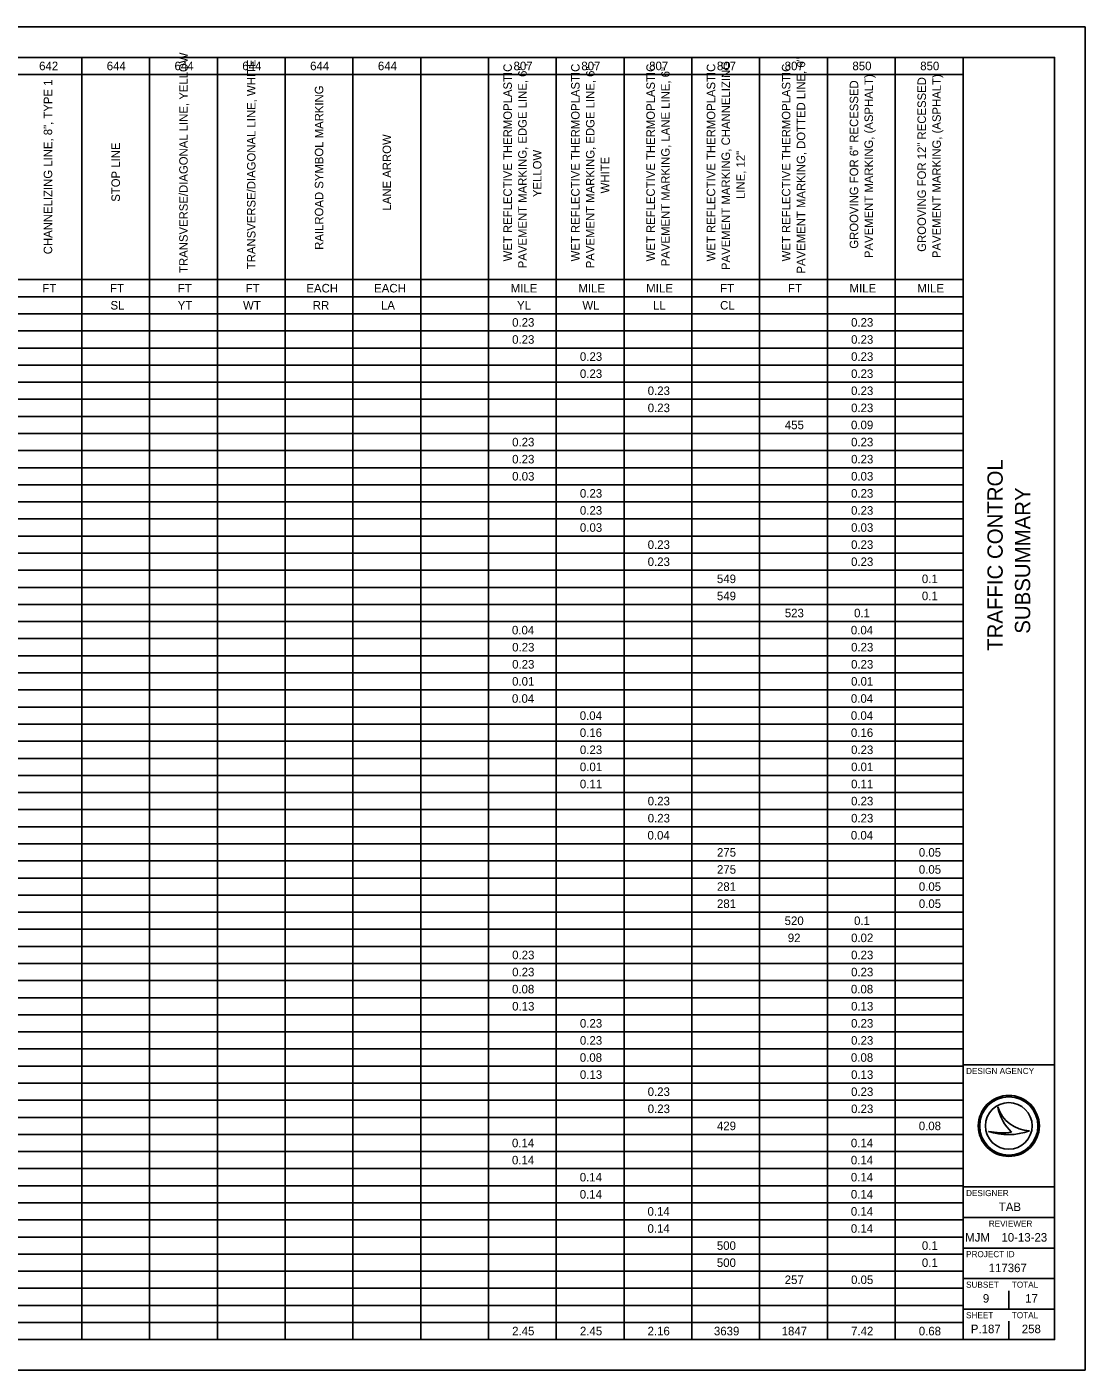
# Model space of a CAD drawing. Extents: x 0 to 34, y 0 to 22.
# Drawn here: x 16.67 to 34, y 0 to 22 of the extents above; entities that cross this region are included whole.
import ezdxf

# ---------------------------------------------------------------- set-up
doc = ezdxf.new("R2010")
doc.units = 0
for name, color, linetype in [('Default', 7, 'Continuous'), ('SH_Border', 7, 'Continuous'), ('SH_Cut_Line', 7, 'Continuous'), ('SH_Data', 7, 'Continuous')]:
    doc.layers.add(name, color=color, linetype=linetype)

msp = doc.modelspace()

# ---------------------------------------------------------------- linework, layer by layer
at = {"layer": 'Default'}
for p, q in [((1.5, 21.5), (32, 21.5)), ((17.566, 21.5), (17.566, 0.5)), ((18.677, 21.5), (18.677, 0.5)), ((19.787, 21.5), (19.787, 0.5)), ((20.897, 21.5), (20.897, 0.5)), ((22.007, 21.5), (22.007, 0.5)), ((23.118, 21.5), (23.118, 0.5)), ((24.228, 21.5), (24.228, 0.5)), ((25.338, 21.5), (25.338, 0.5)), ((26.449, 21.5), (26.449, 0.5)), ((27.559, 21.5), (27.559, 0.5)), ((28.669, 21.5), (28.669, 0.5)), ((29.779, 21.5), (29.779, 0.5)), ((30.89, 21.5), (30.89, 0.5)), ((32, 21.5), (32, 0.5)), ((8.684, 21.22), (32, 21.22)), ((8.684, 17.86), (32, 17.86)), ((1.5, 17.58), (32, 17.58)), ((1.5, 17.3), (32, 17.3)), ((1.5, 17.02), (32, 17.02)), ((1.5, 16.74), (32, 16.74)), ((1.5, 16.46), (32, 16.46)), ((1.5, 16.18), (32, 16.18)), ((1.5, 15.9), (32, 15.9)), ((1.5, 15.62), (32, 15.62)), ((1.5, 15.34), (32, 15.34)), ((1.5, 15.06), (32, 15.06)), ((1.5, 14.78), (32, 14.78)), ((1.5, 14.5), (32, 14.5)), ((1.5, 14.22), (32, 14.22)), ((1.5, 13.94), (32, 13.94)), ((1.5, 13.66), (32, 13.66)), ((1.5, 13.38), (32, 13.38)), ((1.5, 13.1), (32, 13.1)), ((1.5, 12.82), (32, 12.82)), ((1.5, 12.54), (32, 12.54)), ((1.5, 12.26), (32, 12.26)), ((1.5, 11.98), (32, 11.98)), ((1.5, 11.7), (32, 11.7)), ((1.5, 11.42), (32, 11.42)), ((1.5, 11.14), (32, 11.14)), ((1.5, 10.86), (32, 10.86)), ((1.5, 10.58), (32, 10.58)), ((1.5, 10.3), (32, 10.3)), ((1.5, 10.02), (32, 10.02)), ((1.5, 9.74), (32, 9.74)), ((1.5, 9.46), (32, 9.46)), ((1.5, 9.18), (32, 9.18)), ((1.5, 8.9), (32, 8.9)), ((1.5, 8.62), (32, 8.62)), ((1.5, 8.34), (32, 8.34)), ((1.5, 8.06), (32, 8.06)), ((1.5, 7.78), (32, 7.78)), ((1.5, 7.5), (32, 7.5)), ((1.5, 7.22), (32, 7.22)), ((1.5, 6.94), (32, 6.94)), ((1.5, 6.66), (32, 6.66)), ((1.5, 6.38), (32, 6.38)), ((1.5, 6.1), (32, 6.1)), ((1.5, 5.82), (32, 5.82)), ((1.5, 5.54), (32, 5.54)), ((1.5, 5.26), (32, 5.26)), ((1.5, 4.98), (32, 4.98)), ((1.5, 4.7), (32, 4.7)), ((1.5, 4.42), (32, 4.42)), ((1.5, 4.14), (32, 4.14)), ((1.5, 3.86), (32, 3.86)), ((1.5, 3.58), (32, 3.58)), ((1.5, 3.3), (32, 3.3)), ((1.5, 3.02), (32, 3.02)), ((1.5, 2.74), (32, 2.74)), ((1.5, 2.46), (32, 2.46)), ((1.5, 2.18), (32, 2.18)), ((1.5, 1.9), (32, 1.9)), ((1.5, 1.62), (32, 1.62)), ((1.5, 1.34), (32, 1.34)), ((1.5, 1.06), (32, 1.06)), ((1.5, 0.78), (32, 0.78)), ((1.5, 0.5), (32, 0.5))]:
    msp.add_line(p, q, dxfattribs=at)
at = {"layer": 'SH_Border'}
for p, q in [((32, 0.5), (32, 21.5)), ((32, 5), (33.5, 5)), ((32, 3), (33.5, 3)), ((32, 2.5), (33.5, 2.5)), ((32, 2), (33.5, 2)), ((32, 1.5), (33.5, 1.5)), ((32, 1), (33.5, 1))]:
    msp.add_line(p, q, dxfattribs=at)
msp.add_lwpolyline([(1.5, 21.5), (33.5, 21.5), (33.5, 0.5), (1.5, 0.5)], close=True, dxfattribs=at)
at = {"layer": 'SH_Cut_Line'}
msp.add_lwpolyline([(0, 0), (34, 0), (34, 22), (0, 22)], close=True, dxfattribs=at)
at = {"layer": 'SH_Data'}
for p, q in [((32.567, 4.31), (32.567, 4.31)), ((32.75, 4), (32.75, 4)), ((32.417, 3.91), (32.417, 3.91)), ((33.087, 3.919), (33.087, 3.919)), ((32.75, 1), (32.75, 1.3)), ((32.375, 0.675), (32.375, 0.675)), ((32.75, 0.5), (32.75, 0.8))]:
    msp.add_line(p, q, dxfattribs=at)
for radius in [0.5, 0.477, 0.477, 0.382]:
    msp.add_circle((32.75, 4), radius, dxfattribs=at)
for centre, radius, start, end in [((33.116, 4.498), 0.58, 198.9257, 198.9319), ((33.347, 4.47), 0.796, 191.6379, 191.6421), ((33.116, 4.498), 0.58, 198.9319, 267.1657), ((33.347, 4.47), 0.796, 191.6421, 226.0947), ((32.739, 4.87), 1.013, 251.4576, 290.0832), ((32.648, 5.154), 1.266, 259.4964, 259.4995), ((32.739, 4.87), 1.013, 251.4527, 251.4576), ((32.648, 5.154), 1.266, 259.4995, 276.6672)]:
    msp.add_arc(centre, radius, start, end, dxfattribs=at)

# ---------------------------------------------------------------- texts
at = {"layer": 'Default'}
for s, height, p in [('TRANSVERSE/DIAGONAL LINE, YELLOW', 0.13878, (19.301, 17.97)), ('TRANSVERSE/DIAGONAL LINE, WHITE', 0.13878, (20.411, 18.031)), ('WET REFLECTIVE THERMOPLASTIC ', 0.13878, (24.61, 18.159)), ('PAVEMENT MARKING, EDGE LINE, 6", ', 0.13878, (24.853, 18.046)), ('WET REFLECTIVE THERMOPLASTIC ', 0.13878, (25.72, 18.159)), ('PAVEMENT MARKING, EDGE LINE, 6", ', 0.13878, (25.963, 18.046)), ('WET REFLECTIVE THERMOPLASTIC ', 0.13878, (26.952, 18.159)), ('WET REFLECTIVE THERMOPLASTIC ', 0.13878, (27.941, 18.159)), ('PAVEMENT MARKING, CHANNELIZING ', 0.13878, (28.183, 18.017)), ('WET REFLECTIVE THERMOPLASTIC ', 0.13878, (29.172, 18.159)), ('PAVEMENT MARKING, DOTTED LINE, 6"', 0.13878, (29.415, 17.96)), ('CHANNELIZING LINE, 8", TYPE 1', 0.13878, (17.081, 18.276)), ('PAVEMENT MARKING, LANE LINE, 6"', 0.13878, (27.195, 18.08)), ('PAVEMENT MARKING, (ASPHALT)', 0.13878, (30.525, 18.213)), ('GROOVING FOR 12" RECESSED ', 0.13878, (31.393, 18.316)), ('PAVEMENT MARKING, (ASPHALT)', 0.13878, (31.636, 18.213)), ('RAILROAD SYMBOL MARKING', 0.13878, (21.522, 18.349)), ('GROOVING FOR 6" RECESSED ', 0.13878, (30.283, 18.367)), ('STOP LINE', 0.1388, (18.191, 19.136)), ('LANE ARROW', 0.1388, (22.632, 18.992)), ('YELLOW', 0.1388, (25.095, 19.212)), ('WHITE', 0.1388, (26.206, 19.273)), ('LINE, 12"', 0.1388, (28.426, 19.181))]:
    msp.add_text(s, height=height, rotation=90, dxfattribs=at).set_placement(p)
for s, p in [('642', (16.867, 21.29)), ('644', (17.975, 21.29)), ('644', (19.085, 21.29)), ('644', (20.195, 21.29)), ('644', (21.306, 21.29)), ('644', (22.416, 21.29)), ('807', (24.638, 21.29)), ('807', (25.748, 21.29)), ('807', (26.859, 21.29)), ('807', (27.969, 21.29)), ('807', (29.079, 21.29)), ('850', (30.188, 21.29)), ('850', (31.299, 21.29)), ('FT', (16.919, 17.65)), ('FT', (18.029, 17.65)), ('FT', (19.139, 17.65)), ('FT', (20.25, 17.65)), ('EACH', (21.244, 17.65)), ('EACH', (22.354, 17.65)), ('MILE', (24.59, 17.65)), ('MILE', (25.7, 17.65)), ('MILE', (26.811, 17.65)), ('FT', (28.022, 17.65)), ('FT', (29.132, 17.65)), ('MILE', (30.141, 17.65)), ('MILE', (31.252, 17.65)), ('SL', (18.036, 17.37)), ('YT', (19.137, 17.37)), ('WT', (20.207, 17.37)), ('RR', (21.349, 17.37)), ('LA', (22.466, 17.37)), ('YL', (24.695, 17.37)), ('WL', (25.765, 17.37)), ('LL', (26.922, 17.37)), ('CL', (28.021, 17.37)), ('0.23', (24.615, 17.09)), ('0.23', (30.166, 17.09)), ('0.23', (24.615, 16.81)), ('0.23', (30.166, 16.81)), ('0.23', (25.725, 16.53)), ('0.23', (30.166, 16.53)), ('0.23', (25.725, 16.25)), ('0.23', (30.166, 16.25)), ('0.23', (26.835, 15.97)), ('0.23', (30.166, 15.97)), ('0.23', (26.835, 15.69)), ('0.23', (30.166, 15.69)), ('455', (29.081, 15.41)), ('0.09', (30.165, 15.41)), ('0.23', (24.615, 15.13)), ('0.23', (30.166, 15.13)), ('0.23', (24.615, 14.85)), ('0.23', (30.166, 14.85)), ('0.03', (24.615, 14.57)), ('0.03', (30.166, 14.57)), ('0.23', (25.725, 14.29)), ('0.23', (30.166, 14.29)), ('0.23', (25.725, 14.01)), ('0.23', (30.166, 14.01)), ('0.03', (25.725, 13.73)), ('0.03', (30.166, 13.73)), ('0.23', (26.835, 13.45)), ('0.23', (30.166, 13.45)), ('0.23', (26.835, 13.17)), ('0.23', (30.166, 13.17)), ('549', (27.969, 12.89)), ('0.1', (31.326, 12.89)), ('549', (27.969, 12.61)), ('0.1', (31.326, 12.61)), ('523', (29.081, 12.33)), ('0.1', (30.215, 12.33)), ('0.04', (24.612, 12.05)), ('0.04', (30.163, 12.05)), ('0.23', (24.615, 11.77)), ('0.23', (30.166, 11.77)), ('0.23', (24.615, 11.49)), ('0.23', (30.166, 11.49)), ('0.01', (24.614, 11.21)), ('0.01', (30.166, 11.21)), ('0.04', (24.612, 10.93)), ('0.04', (30.163, 10.93)), ('0.04', (25.722, 10.65)), ('0.04', (30.163, 10.65)), ('0.16', (25.723, 10.37)), ('0.16', (30.164, 10.37)), ('0.23', (25.725, 10.09)), ('0.23', (30.166, 10.09)), ('0.01', (25.724, 9.81)), ('0.01', (30.166, 9.81)), ('0.11', (25.724, 9.53)), ('0.11', (30.166, 9.53)), ('0.23', (26.835, 9.25)), ('0.23', (30.166, 9.25)), ('0.23', (26.835, 8.97)), ('0.23', (30.166, 8.97)), ('0.04', (26.832, 8.69)), ('0.04', (30.163, 8.69)), ('275', (27.97, 8.41)), ('0.05', (31.276, 8.41)), ('275', (27.97, 8.13)), ('0.05', (31.276, 8.13)), ('281', (27.97, 7.85)), ('0.05', (31.276, 7.85)), ('281', (27.97, 7.57)), ('0.05', (31.276, 7.57)), ('520', (29.078, 7.29)), ('0.1', (30.215, 7.29)), ('92', (29.13, 7.01)), ('0.02', (30.166, 7.01)), ('0.23', (24.615, 6.73)), ('0.23', (30.166, 6.73)), ('0.23', (24.615, 6.45)), ('0.23', (30.166, 6.45)), ('0.08', (24.613, 6.17)), ('0.08', (30.164, 6.17)), ('0.13', (24.615, 5.89)), ('0.13', (30.166, 5.89)), ('0.23', (25.725, 5.61)), ('0.23', (30.166, 5.61)), ('0.23', (25.725, 5.33)), ('0.23', (30.166, 5.33)), ('0.08', (25.723, 5.05)), ('0.08', (30.164, 5.05)), ('0.13', (25.725, 4.77)), ('0.13', (30.166, 4.77)), ('0.23', (26.835, 4.49)), ('0.23', (30.166, 4.49)), ('0.23', (26.835, 4.21)), ('0.23', (30.166, 4.21)), ('429', (27.969, 3.93)), ('0.08', (31.275, 3.93)), ('0.14', (24.612, 3.65)), ('0.14', (30.163, 3.65)), ('0.14', (24.612, 3.37)), ('0.14', (30.163, 3.37)), ('0.14', (25.722, 3.09)), ('0.14', (30.163, 3.09)), ('0.14', (25.722, 2.81)), ('0.14', (30.163, 2.81)), ('0.14', (26.832, 2.53)), ('0.14', (30.163, 2.53)), ('0.14', (26.832, 2.25)), ('0.14', (30.163, 2.25)), ('500', (27.968, 1.97)), ('0.1', (31.326, 1.97)), ('500', (27.968, 1.69)), ('0.1', (31.326, 1.69)), ('257', (29.079, 1.41)), ('0.05', (30.166, 1.41)), ('2.45', (24.615, 0.57)), ('2.45', (25.725, 0.57)), ('2.16', (26.833, 0.57)), ('3639', (27.92, 0.57)), ('1847', (29.029, 0.57)), ('7.42', (30.166, 0.57)), ('0.68', (31.275, 0.57))]:
    msp.add_text(s, height=0.14, dxfattribs=at).set_placement(p)
at = {"layer": 'SH_Data'}
for s, p in [('TRAFFIC CONTROL', (32.65, 11.78)), ('SUBSUMMARY', (33.1, 12.061))]:
    msp.add_text(s, height=0.25, rotation=90, dxfattribs=at).set_placement(p)
for s, height, p in [('DESIGN AGENCY', 0.1, (32.05, 4.85)), ('DESIGNER', 0.1, (32.05, 2.85)), ('TAB', 0.14, (32.586, 2.605)), ('REVIEWER', 0.1, (32.422, 2.35)), ('MJM', 0.14, (32.035, 2.105)), ('10-13-23', 0.14, (32.629, 2.105)), ('PROJECT ID', 0.1, (32.05, 1.85)), ('117367', 0.14, (32.42, 1.605)), ('SUBSET', 0.1, (32.05, 1.35)), ('TOTAL', 0.1, (32.8, 1.35)), ('9', 0.14, (32.325, 1.105)), ('17', 0.14, (33.018, 1.105)), ('SHEET', 0.1, (32.05, 0.85)), ('TOTAL', 0.1, (32.8, 0.85)), ('P.187', 0.14, (32.128, 0.605)), ('258', 0.14, (32.962, 0.605))]:
    msp.add_text(s, height=height, dxfattribs=at).set_placement(p)

doc.saveas('drawing.dxf')
